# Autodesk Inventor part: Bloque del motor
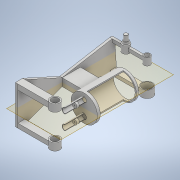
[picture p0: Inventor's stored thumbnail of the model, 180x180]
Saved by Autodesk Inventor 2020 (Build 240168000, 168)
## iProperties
Created: 2019-09
Part Number: Bloque del motor
Material: Generic
Document SubType Name: Modeling
Designer: user
Density: 1 g/cm^3
Appearance: Default
Author: user
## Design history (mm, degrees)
sketch "Sketch1"
  geometry: C1 r 25 at (0, 0); C2 r 27.5 at (0, 0); 1 further point
  constraints: 2 centre point, 2 coincident
  dimensions: "d0" = 50 diameter of C1; "d1" = 55 diameter of C2
extrude "Extrusion1" new body sketch "Sketch1" distance "d2" = 85; taper "d3" = 0 deg
sketch "Sketch2"
  geometry: C1 r 27.5 at (0, 0); C2 r 5 at (0, -15); C3 r 5 at (0, 15); 1 further point
  constraints: 3 centre point, 1 coincident
  dimensions: "d4" = 10 diameter of C2; "d5" = 10 diameter of C3; "d6" = 15 distance of point (0, 0) C2.centre; "d7" = 15 distance of point (0, 0) C3.centre
extrude "Extrusion2" join sketch "Sketch2" distance "d8" = 1; taper "d9" = 0 deg
sketch "Sketch3"
  geometry: L1 (0, -21)-(0, -20); L2 (0, -10)-(0, -9); L3 (0, 9)-(0, 10); L4 (0, 20)-(0, 21); C1 r 5 at (0, -15) reference; C2 r 5 at (0, 15) reference; A1 r 5 centre (0, -15) between (0, -10) and (0, -20); A2 r 5 centre (0, 15) between (0, 20) and (0, 10); A3 r 6 centre (0, -15) between (0, -9) and (0, -21); A4 r 6 centre (0, 15) between (0, 21) and (0, 9); 1 further point
  constraints: 8 end point, 8 point on circle, 4 centre point, 4 coincident, 2 vertical
  dimensions: "d10" = 12 diameter of A4
extrude "Extrusion3" join sketch "Sketch3" distance "d11" = 40; taper "d12" = 0 deg
workplane "Work Plane1"
sketch "Sketch4"
  geometry: C1 r 5 at (0, 15); C2 r 5 at (0, -15) reference; C3 r 5 at (0, -15); C4 r 1 at (0, -15); C5 r 1 at (0, 15); A1 r 5 centre (0, 15) between (0, 20) and (0, 10) reference; 1 further point
  constraints: 4 centre point, 4 coincident
extrude "Extrusion4" join sketch "Sketch4" distance "d14" = 5; taper "d15" = 0 deg
workplane "Work Plane3"
sketch "Sketch5"
  geometry: L1 (27.5, 85)-(-27.5, 85) reference; C1 r 6.5 at (0, 130); C2 r 5 at (0, 130); 1 further point
  constraints: 2 centre point, 1 coincident
  dimensions: "d17" = 13 diameter of C1; "d18" = 45 distance from line of C1.centre L1; "d21" = 10 diameter of C2
extrude "Extrusion5" join sketch "Sketch5" distance "d19" = 15; taper "d20" = 0 deg
workplane "Work Plane4"
sketch "Sketch6"
  geometry: C1 r 6.5 at (0, 130) reference; C2 r 10 at (0, 130); C3 r 11.5 at (0, 130); 1 further point
  constraints: 2 centre point, 2 coincident
  dimensions: "d23" = 20 diameter of C2; "d24" = 23 diameter of C3
extrude "Extrusion6" join sketch "Sketch6" distance "d25" = 15; taper "d26" = 0 deg
workplane "Work Plane5"
sketch "Sketch7"
  geometry: L1 (23, 8)-(61, 8); L2 (61, 8)-(61, -8); L3 (61, -8)-(23, -8); L4 (23, -8)-(23, 8); L5 (127.5, 26)-(132.5, 26); L6 (132.5, 26)-(132.5, 19); L7 (132.5, 19)-(127.5, 19); L8 (127.5, 19)-(127.5, 26); L9 (123, -29)-(136, -29); L10 (136, -29)-(136, -36); L11 (136, -36)-(123, -36); L12 (123, -36)-(123, -29); L13 (135, 15)-(125, 15) reference; L14 (136.5, 30)-(123.5, 30) reference; L15 (120, -25)-(140, -25) reference; L16 (140, -40)-(120, -40) reference; 1 further point
  constraints: 24 end point, 6 parallel, 3 horizontal, 3 perpendicular
  dimensions: "d28" = 4 distance between parallel lines of L13 L7; "d29" = 4 distance between parallel lines of L14 L5; "d30" = 4 distance from line of L14.end L8; "d31" = 4 distance from line of L14.start L6; "d32" = 4 distance between parallel lines of L15 L9; "d33" = 4 distance between parallel lines of L16 L11
extrude "Extrusion7" join sketch "Sketch7" stored distance "d34" = 15; taper "d35" = 0 deg
sketch "Sketch8"
  geometry: L1 (61, 8)-(23, 8) reference; L2 (23, -8)-(61, -8) reference; L3 (23, -8)-(23, 8); L4 (136, -29)-(123, -29) reference; L5 (136, -29)-(136, -36); L6 (136, -36)-(123, -36); L7 (127.5, 26)-(127.5, 19) reference; L8 (132.5, 26)-(127.5, 26) reference; L9 (132.5, 26)-(127.5, 26); L10 (23, -8)-(123, -36); L11 (136, -29)-(132.5, 26); L12 (127.5, 26)-(23, 8); 1 further point
  constraints: 14 end point
extrude "Extrusion8" join sketch "Sketch8" distance "d36" = 5; taper "d37" = 0 deg
workplane "Work Plane6"
sketch "Sketch9"
  geometry: L1 (-6, -41)-(0, -41) reference; C1 r 7.5 at (0, -61.72); C2 r 10 at (0, -61.72); 1 further point
  constraints: 2 centre point, 1 coincident
  dimensions: "d39" = 15 diameter of C1; "d40" = 20 diameter of C2; "d50" = 20.72 distance from line of L1 C1.centre
extrude "Extrusion9" join sketch "Sketch9" distance "d41" = 15; taper "d42" = 0 deg
workplane "Work Plane7"
sketch "Sketch13"
  geometry: C1 r 7.5 at (0, -61.72) reference; C2 r 7.5 at (0, -61.72); C3 r 10 at (0, -61.72); 1 further point
  constraints: 2 centre point, 2 coincident
extrude "Extrusion13" join sketch "Sketch13" distance "d51" = 15; taper "d52" = 0 deg
sketch "Sketch14"
  geometry: L1 (37, -69)-(28, -69); L2 (28, -69)-(28, -54); L3 (28, -54)-(37, -54); L4 (37, -54)-(37, -69); L5 (-30, -69.22)-(-45, -69.22) reference; L6 (-32, -69.22)-(-43, -69.22); L7 (-43, -69.22)-(-43, -54); L8 (-43, -54)-(-32, -54); L9 (-32, -54)-(-32, -69.22); 1 further point
  constraints: 16 end point, 4 parallel, 2 horizontal, 2 perpendicular, 2 point on line
extrude "Extrusion14" join sketch "Sketch14" stored distance "d53" = 15; taper "d54" = 0 deg
sketch "Sketch15"
  geometry: L1 (-43, -54)-(-32, -54) reference; L2 (-43, -54)-(-8, 23); L3 (-8, 23)-(8, 23); L4 (37, -54)-(37, -69) reference; L5 (8, 23)-(37, -54); L6 (28, -69)-(37, -69) reference; L7 (37, -54)-(37, -69); L8 (-43, -69.22)-(-32, -69.22) reference; L9 (37, -69)-(-43, -69.22); L10 (-43, -69.22)-(-43, -54); 1 further point
  constraints: 12 end point, 1 horizontal, 1 perpendicular
extrude "Extrusion15" join sketch "Sketch15" distance "d55" = 5; taper "d56" = 0 deg
sketch "Sketch16"
  geometry: L1 (37, 5)-(0, 5); L2 (0, 5)-(0, 80); L3 (0, 80)-(37, 80); L4 (37, 80)-(37, 5); 1 further point
  constraints: 8 end point, 2 parallel, 1 horizontal, 1 perpendicular
extrude "Extrusion16" cut sketch "Sketch16" extent not by distance; stored distance "d57" = 5; taper "d58" = 0 deg
sketch "Sketch17"
  geometry: C1 r 7.5 at (44, 0); 1 further point
  constraints: 1 centre point
  dimensions: "d67" = 15 diameter of C1
extrude "Extrusion17" join sketch "Sketch17" distance "d59" = 15; taper "d60" = 0 deg
sketch "Sketch18"
  geometry: C1 r 7.5 at (0, 0) reference; C2 r 5 at (0, 0); 1 further point
  constraints: 1 centre point, 1 coincident
  dimensions: "d61" = 10 diameter of C2
extrude "Extrusion18" join sketch "Sketch18" distance "d62" = 5; taper "d63" = 0 deg
sketch "Sketch19"
  geometry: C1 r 4 at (0, 0); 1 further point
  constraints: 1 centre point
  dimensions: "d68" = 8 diameter of C1
extrude "Extrusion19" join sketch "Sketch19" distance "d69" = 11; taper "d70" = 0 deg
chamfer "Chamfer2" distance "d71" = 0.5; stored, may be unused: second distance "d72" = 2, angle "d73" = 45 deg
workplane "Work Plane8"
workplane "Work Plane9"
body "Solid1"
other parameters: "d16" = 15, "d22" = -25, "d38" = -25, "d74" = 15, "d75" = -15
